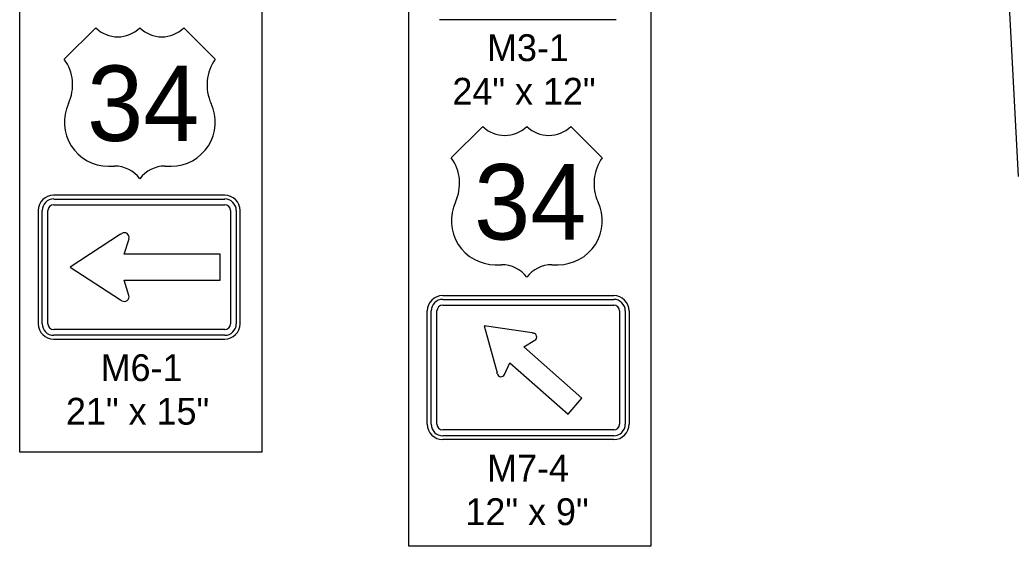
# Model space of a CAD drawing. Extents: x 10133 to 81668, y 6132 to 11018.
# Drawn here: x 10520.3 to 10816.6, y 8502.2 to 8659.2 of the extents above; entities that cross this region are included whole.
import ezdxf

# ---------------------------------------------------------------- set-up
doc = ezdxf.new("R2010")
doc.units = 0
for name, color, linetype in [('dsnTextFinalPlan', 7, 'Continuous'), ('Level 10', 7, 'Continuous'), ('Level 4', 7, 'Continuous'), ('Level 5', 7, 'Continuous')]:
    doc.layers.add(name, color=color, linetype=linetype)

msp = doc.modelspace()

# ---------------------------------------------------------------- linework, layer by layer
at = {"layer": 'dsnTextFinalPlan'}
for p, q in [((10646.28, 8576.97), (10697.25, 8576.97)), ((10641.7, 8538.6), (10641.7, 8572.39)), ((10701.83, 8572.39), (10701.83, 8538.6)), ((10697.25, 8534.02), (10646.28, 8534.02))]:
    msp.add_line(p, q, dxfattribs=at)
for points in [[(10785.14, 9142), (10794.64, 9051.15), (10817.78, 8612.5)], [(10672.99, 8565.84), (10658.62, 8567.9), (10662.48, 8553.93)], [(10664.69, 8553.41), (10666.32, 8556.93), (10683.64, 8541.64), (10687.8, 8546.35), (10670.47, 8561.64), (10673.77, 8563.67)]]:
    msp.add_lwpolyline(points, dxfattribs=at)
for points in [[(10520.28, 8842.44), (10592.34, 8842.44), (10592.34, 8530.22), (10520.28, 8530.22)], [(10520.28, 8842.44), (10592.34, 8842.44), (10592.34, 8530.22), (10520.28, 8530.22)], [(10520.28, 8842.44), (10592.34, 8842.44), (10592.34, 8530.22), (10520.28, 8530.22)], [(10636.23, 8814.46), (10708.3, 8814.46), (10708.3, 8502.24), (10636.23, 8502.24)], [(10636.23, 8814.46), (10708.3, 8814.46), (10708.3, 8502.24), (10636.23, 8502.24)]]:
    msp.add_lwpolyline(points, close=True, dxfattribs=at)
for centre, radius, start, end in [((10646.28, 8572.39), 4.58, 90, 180), ((10697.25, 8572.39), 4.58, 0, 90), ((10689.52, 8680.61), 115.96, 261.8049, 261.9654), ((10673.15, 8564.64), 1.16, 302.6073, 81.9654), ((10550.7, 8523.07), 115.96, 15.2659, 15.4333), ((10663.67, 8553.9), 1.14, 195.2659, 334.5454), ((10646.28, 8538.6), 4.58, 180, 270), ((10697.25, 8538.6), 4.58, 270, 0)]:
    msp.add_arc(centre, radius, start, end, dxfattribs=at)
at = {"layer": 'Level 10'}
for p, q in [((10698, 8659.2), (10645.38, 8659.2)), ((10581.31, 8606.92), (10530.34, 8606.92)), ((10581.31, 8606.92), (10530.34, 8606.92)), ((10530.35, 8605.77), (10581.32, 8605.77)), ((10530.35, 8605.77), (10581.32, 8605.77)), ((10525.76, 8602.34), (10525.76, 8568.55)), ((10525.76, 8602.34), (10525.76, 8568.55)), ((10526.92, 8568.55), (10526.92, 8602.34)), ((10526.92, 8568.55), (10526.92, 8602.34)), ((10528.63, 8568.55), (10528.63, 8602.34)), ((10528.63, 8568.55), (10528.63, 8602.34)), ((10530.35, 8604.05), (10581.32, 8604.05)), ((10530.35, 8604.05), (10581.32, 8604.05)), ((10583.04, 8602.34), (10583.04, 8568.55)), ((10583.04, 8602.34), (10583.04, 8568.55)), ((10584.75, 8602.34), (10584.75, 8568.55)), ((10584.75, 8602.34), (10584.75, 8568.55)), ((10585.89, 8568.55), (10585.89, 8602.34)), ((10585.89, 8568.55), (10585.89, 8602.34)), ((10646.28, 8575.83), (10697.25, 8575.83)), ((10642.85, 8538.6), (10642.85, 8572.39)), ((10644.57, 8538.6), (10644.57, 8572.39)), ((10646.28, 8574.11), (10697.25, 8574.11)), ((10698.97, 8572.39), (10698.97, 8538.6)), ((10700.69, 8572.39), (10700.69, 8538.6)), ((10581.32, 8566.83), (10530.35, 8566.83)), ((10581.32, 8566.83), (10530.35, 8566.83)), ((10530.34, 8563.97), (10581.31, 8563.97)), ((10530.34, 8563.97), (10581.31, 8563.97)), ((10581.32, 8565.11), (10530.35, 8565.11)), ((10581.32, 8565.11), (10530.35, 8565.11)), ((10697.25, 8536.89), (10646.28, 8536.89)), ((10697.25, 8535.17), (10646.28, 8535.17))]:
    msp.add_line(p, q, dxfattribs=at)
for points in [[(10550.3, 8595.26), (10535.31, 8585.44), (10550.3, 8575.66)], [(10550.3, 8595.26), (10535.31, 8585.44), (10550.3, 8575.66)], [(10552.77, 8576.99), (10551.4, 8581.57), (10579.93, 8581.57), (10579.93, 8589.32), (10551.4, 8589.32), (10552.8, 8593.89)], [(10552.77, 8576.99), (10551.4, 8581.57), (10579.93, 8581.57), (10579.93, 8589.32), (10551.4, 8589.32), (10552.8, 8593.89)]]:
    msp.add_lwpolyline(points, dxfattribs=at)
for centre, radius, start, end in [((10530.34, 8602.34), 4.58, 90, 180), ((10530.34, 8602.34), 4.58, 90, 180), ((10530.35, 8602.34), 3.44, 90, 180), ((10530.35, 8602.34), 3.44, 90, 180), ((10581.31, 8602.34), 4.58, 360, 90), ((10581.31, 8602.34), 4.58, 360, 90), ((10581.32, 8602.34), 3.44, 0, 90), ((10581.32, 8602.34), 3.44, 0, 90), ((10530.35, 8602.34), 1.72, 90, 180), ((10530.35, 8602.34), 1.72, 90, 180), ((10581.32, 8602.34), 1.72, 0, 90), ((10581.32, 8602.34), 1.72, 0, 90), ((10471.85, 8715.02), 143.16, 303.2286, 303.3891), ((10471.85, 8715.02), 143.16, 303.2286, 303.3891), ((10551.42, 8594.29), 1.43, 344.0309, 123.3891), ((10551.42, 8594.29), 1.43, 344.0309, 123.3891), ((10472.03, 8455.78), 143.16, 56.6896, 56.857), ((10472.03, 8455.78), 143.16, 56.6896, 56.857), ((10551.42, 8576.6), 1.4, 236.6896, 15.9691), ((10551.42, 8576.6), 1.4, 236.6896, 15.9691), ((10646.28, 8572.39), 3.44, 90, 180), ((10697.25, 8572.39), 3.44, 0, 90), ((10646.28, 8572.39), 1.72, 90, 180), ((10697.25, 8572.39), 1.72, 0, 90), ((10530.34, 8568.55), 4.58, 180, 270), ((10530.34, 8568.55), 4.58, 180, 270), ((10530.35, 8568.55), 3.44, 180, 270), ((10530.35, 8568.55), 3.44, 180, 270), ((10530.35, 8568.55), 1.72, 180, 270), ((10530.35, 8568.55), 1.72, 180, 270), ((10581.31, 8568.55), 4.58, 270, 0), ((10581.31, 8568.55), 4.58, 270, 0), ((10581.32, 8568.55), 3.44, 270, 0), ((10581.32, 8568.55), 1.72, 270, 0), ((10581.32, 8568.55), 3.44, 270, 0), ((10581.32, 8568.55), 1.72, 270, 0), ((10646.28, 8538.6), 3.44, 180, 270), ((10646.28, 8538.6), 1.72, 180, 270), ((10697.25, 8538.6), 3.44, 270, 0), ((10697.25, 8538.6), 1.72, 270, 0)]:
    msp.add_arc(centre, radius, start, end, dxfattribs=at)
at = {"layer": 'Level 4'}
for p, q in [((10542.89, 8656.83), (10533.51, 8647.45)), ((10542.89, 8656.83), (10533.51, 8647.45)), ((10542.89, 8656.83), (10533.51, 8647.45)), ((10578.51, 8647.45), (10569.14, 8656.83)), ((10578.51, 8647.45), (10569.14, 8656.83)), ((10578.51, 8647.45), (10569.14, 8656.83)), ((10658.22, 8627.43), (10648.84, 8618.05)), ((10658.22, 8627.43), (10648.84, 8618.05)), ((10693.84, 8618.05), (10684.47, 8627.43)), ((10693.84, 8618.05), (10684.47, 8627.43)), ((10546.64, 8615.58), (10548.51, 8615.58)), ((10546.64, 8615.58), (10548.51, 8615.58)), ((10546.64, 8615.58), (10548.51, 8615.58)), ((10563.51, 8615.58), (10565.39, 8615.58)), ((10563.51, 8615.58), (10565.39, 8615.58)), ((10563.51, 8615.58), (10565.39, 8615.58)), ((10661.97, 8586.18), (10663.84, 8586.18)), ((10661.97, 8586.18), (10663.84, 8586.18)), ((10678.84, 8586.18), (10680.72, 8586.18)), ((10678.84, 8586.18), (10680.72, 8586.18))]:
    msp.add_line(p, q, dxfattribs=at)
for centre, radius, start, end in [((10549.45, 8663.52), 9.38, 225.5729, 314.4272), ((10549.45, 8663.52), 9.38, 225.5729, 314.4272), ((10549.45, 8663.52), 9.38, 225.5729, 314.4272), ((10562.58, 8663.52), 9.38, 225.5729, 314.4272), ((10562.58, 8663.52), 9.38, 225.5729, 314.4272), ((10562.58, 8663.52), 9.38, 225.5729, 314.4272), ((10522.85, 8639.8), 13.13, 334.9895, 35.6629), ((10522.85, 8639.8), 13.13, 334.9895, 35.6629), ((10522.85, 8639.8), 13.13, 334.9895, 35.6629), ((10589.18, 8639.8), 13.13, 144.3372, 205.01), ((10589.18, 8639.8), 13.13, 144.3372, 205.01), ((10589.18, 8639.8), 13.13, 144.3372, 205.01), ((10546.64, 8628.7), 13.13, 154.9897, 270.0001), ((10546.64, 8628.7), 13.13, 154.9897, 270.0001), ((10546.64, 8628.7), 13.13, 154.9897, 270.0001), ((10565.39, 8628.7), 13.13, 270.0001, 25.0104), ((10565.39, 8628.7), 13.13, 270.0001, 25.0104), ((10565.39, 8628.7), 13.13, 270.0001, 25.0104), ((10664.78, 8634.12), 9.38, 225.5729, 314.4272), ((10664.78, 8634.12), 9.38, 225.5729, 314.4272), ((10677.91, 8634.12), 9.38, 225.5729, 314.4272), ((10677.91, 8634.12), 9.38, 225.5729, 314.4272), ((10638.18, 8610.4), 13.13, 334.9895, 35.6629), ((10638.18, 8610.4), 13.13, 334.9895, 35.6629), ((10704.51, 8610.4), 13.13, 144.3372, 205.01), ((10704.51, 8610.4), 13.13, 144.3372, 205.01), ((10548.51, 8606.2), 9.38, 36.8699, 90.0002), ((10548.51, 8606.2), 9.38, 36.8699, 90.0002), ((10548.51, 8606.2), 9.38, 36.8699, 90.0002), ((10563.51, 8606.2), 9.38, 90.0002, 143.13), ((10563.51, 8606.2), 9.38, 90.0002, 143.13), ((10563.51, 8606.2), 9.38, 90.0002, 143.13), ((10661.97, 8599.3), 13.13, 154.9897, 270.0001), ((10661.97, 8599.3), 13.13, 154.9897, 270.0001), ((10680.72, 8599.3), 13.13, 270.0001, 25.0104), ((10680.72, 8599.3), 13.13, 270.0001, 25.0104), ((10663.84, 8576.8), 9.38, 36.8699, 90.0002), ((10663.84, 8576.8), 9.38, 36.8699, 90.0002), ((10678.84, 8576.8), 9.38, 90.0002, 143.13), ((10678.84, 8576.8), 9.38, 90.0002, 143.13)]:
    msp.add_arc(centre, radius, start, end, dxfattribs=at)

# ---------------------------------------------------------------- texts
for p in [(10540.31, 8623.08), (10540.31, 8623.08), (10540.31, 8623.08), (10655.64, 8593.68), (10655.64, 8593.68)]:
    msp.add_text('34', height=22.5, dxfattribs=at).set_placement(p)
at = {"layer": 'Level 5'}
for s, p in [('M3-1', (10659.51, 8646.9)), ('24" x 12"', (10649.18, 8633.9)), ('M6-1', (10544.35, 8551.46)), ('M6-1', (10544.35, 8551.46)), ('21" x 15"', (10534.02, 8538.46)), ('21" x 15"', (10534.02, 8538.46)), ('M7-4', (10659.53, 8521.51)), ('12" x 9"', (10653.06, 8508.51))]:
    msp.add_text(s, height=8, dxfattribs=at).set_placement(p)

doc.saveas('drawing.dxf')
